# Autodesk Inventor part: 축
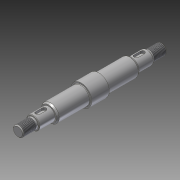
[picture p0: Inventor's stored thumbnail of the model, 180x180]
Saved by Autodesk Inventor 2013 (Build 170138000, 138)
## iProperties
Created: 2018-11
Part Number: 축
Material: 강철, 연강
Document SubType Name: Modeling
Designer: mduedu
Density: 1 g/cm^3
Author: mduedu
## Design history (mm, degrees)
sketch "스케치1"
  geometry: L1 (-10, 0)-(10, 0); L2 (10, 0)-(10, 12); L3 (10, 12)-(-10, 12); L4 (-10, 12)-(-10, 0); L5 (-10, 0)-(-65, 0); L6 (-65, 0)-(-65, 7.5); L7 (-65, 7.5)-(-47, 7.5); L8 (-10, 7.5)-(-10, 0); L9 (-65, 0)-(-82, 0); L10 (-82, 0)-(-82, 6); L11 (-82, 6)-(-65, 6); L12 (-65, 6)-(-65, 0); L13 (0, 0)-(0, 12); L14 (10, 0)-(65, 0); L15 (65, 0)-(65, 7.5); L16 (65, 7.5)-(47, 7.5); L17 (10, 7.5)-(10, 0); L18 (65, 0)-(82, 0); L19 (82, 0)-(82, 6); L20 (82, 6)-(65, 6); L21 (65, 6)-(65, 0); L22 (-47, 7.5)-(-47, 8.85); L23 (-45.008, 10)-(-10, 10); L24 (10, 10)-(45.008, 10); L25 (47, 8.85)-(47, 7.5); L26 (-47, 8.85)-(-45.008, 10); L27 (47, 8.85)-(45.008, 10); 1 further point
  constraints: 54 end point, 9 parallel, 6 symmetric about line, 4 horizontal, 4 perpendicular, 2 midpoint, 2 point on line, 1 coincident
  dimensions: "d0" = 24 diameter of L3 L1; "d2" = 15 diameter of L7 L5; "d3" = 12 diameter of L11 L9; "d4" = 20 distance of L2.end L3.end; "d5" = 55 distance of L6.end L8.start; "d6" = 164 distance between parallel lines of L19 L10; "d24" = 20 diameter of L23 L5; "d25" = 18 distance of L6.end L7.end; "d26" = 18 distance of L15.end L16.end; "d27" = 20 diameter of L24 L14; "d28" = 55 distance between parallel lines of L15 L2; "d29" = 30 deg angle of L23 L26; "d30" = 17.7 diameter of L22.end L5; "d31" = 30 deg angle of L24 L27; "d32" = 17.7 diameter of L25.start L14
revolve "회전1" sketch "스케치1" stored, may be unused: angle "d7" = 90 deg
fillet "모깎기1" dims "d8" = 0.6
node "작업 평면1"
sketch "스케치2" dims "d11" = 12
  geometry: L1 (-3.5, 2.5)-(3.5, 2.5); L2 (3.5, 2.5)-(3.5, -2.5); L3 (3.5, -2.5)-(-3.5, -2.5); L4 (-3.5, -2.5)-(-3.5, 2.5); L5 (9, 7.5)-(9, -7.5) reference; 3 further points
  constraints: 8 end point, 2 midpoint, 2 parallel, 2 vertical alignment, 1 horizontal, 1 horizontal alignment, 1 perpendicular, 4 other
  dimensions: "d9" = 3 dimension on L5; "d10" = 5 distance between parallel lines of L3 L1
extrude "돌출1" cut sketch "스케치2" distance "d12" = 3; taper "d13" = 0 deg
chamfer "모따기1" distance "d14" = 0.5; stored, may be unused: second distance "d15" = 2, angle "d16" = 45 deg
feature "스레드1" dims "d17" = 15, "d18" = 0
feature "스레드2" dims "d19" = 15, "d20" = 0
chamfer "모따기2" distance "d21" = 1; stored, may be unused: second distance "d22" = 2, angle "d23" = 45 deg
node "솔리드1"
mirror "대칭1"
